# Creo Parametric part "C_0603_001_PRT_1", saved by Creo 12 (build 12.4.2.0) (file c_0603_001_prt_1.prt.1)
Units: Custom; MM, KILOGRAM, SECS

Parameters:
  PTC_WM_ITERATION = "0"
  PTC_WM_VERSION = "-.0"
  PTC_WM_LIFECYCLE_STATE = "In Work"
  PTC_WM_LIFECYCLE = "MO_CADDocument"
  PTC_WM_CREATED_BY = "Maximilian Roepper (Z0017RMS: MO)"
  PTC_WM_CREATED_ON = "18-Sep-26 11:36:42 AM"
  PTC_WM_MODIFIED_BY = "Maximilian Roepper (Z0017RMS: MO)"
  PTC_WM_MODIFIED_ON = "18-Sep-26 11:36:46 AM"
  PDMLINKNUMBER = "PDM000071455255"
  PTC_WM_NAME = "c_0603_001_prt_1.prt"
  PTC_WM_NUMBER = "PDM000071455255"

Other parameters: WEIGHT, WEIGHT_FACTOR, WEIGHT_ADD, _MASS_TEMP, _DIFF_TEMP, MC_ERRORS, SUPPLIER

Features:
  1. coordinate system
  2. datum plane "PRT_YZ"
  3. datum plane "PRT_XY"
  4. datum plane "PRT_XZ"
  5. coordinate system
  6. datum axis
  7. datum axis
  8. datum axis
  9. coordinate system
  10. imported feature
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
Other named items: PRT, SIEMENS_MO, DRW_VIEW_ORG, PRT_X, PRT_Y, PRT_Z, CS0, ROUGH_GROB

Layers: 00_STD_CSYS-KSYS, 01_STD_PLANES-EBENEN, 02_STD_AXES-ACHSEN, 03_STD_CSYS-KSYS, 24_IMPORT_FEAT-IMPORT_KE

Surfaces: 16 plane, 12 cylinder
